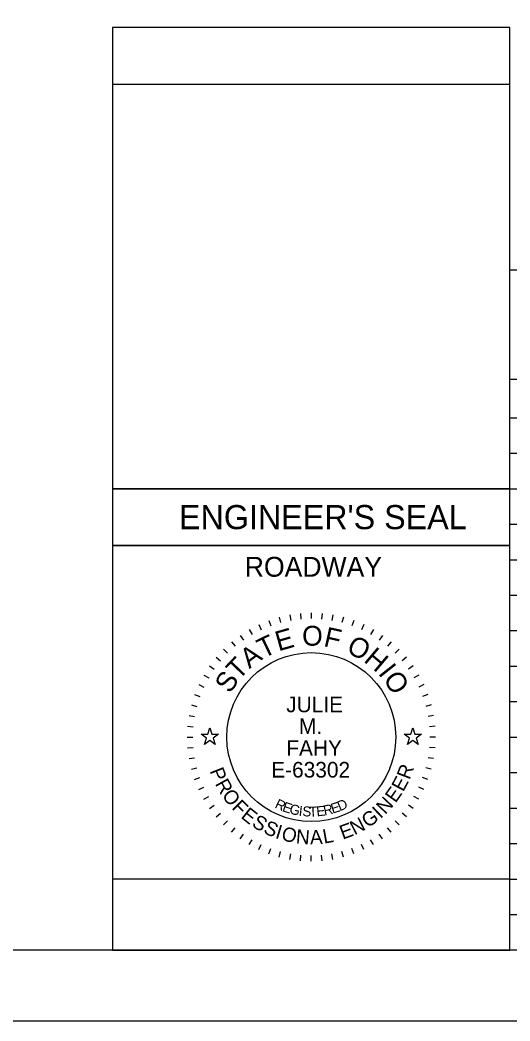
# Model space of a CAD drawing. Extents: x 0 to 34, y 0 to 22.
# Drawn here: x 6.7 to 10.15, y 0 to 7.05 of the extents above; entities that cross this region are included whole.
import ezdxf

# ---------------------------------------------------------------- set-up
doc = ezdxf.new("R2010")
doc.units = 0
for name, color, linetype in [('SH_Border', 7, 'Continuous'), ('SH_Cut_Line', 7, 'Continuous'), ('SH_Data', 7, 'Continuous'), ('SH_Seal', 7, 'Continuous')]:
    doc.layers.add(name, color=color, linetype=linetype)

msp = doc.modelspace()

# ---------------------------------------------------------------- linework, layer by layer
at = {"layer": 'SH_Border'}
msp.add_lwpolyline([(1.5, 21.5), (33.5, 21.5), (33.5, 0.5), (1.5, 0.5)], close=True, dxfattribs=at)
at = {"layer": 'SH_Cut_Line'}
msp.add_lwpolyline([(0, 0), (34, 0), (34, 22), (0, 22)], close=True, dxfattribs=at)
at = {"layer": 'SH_Data'}
for p, q in [((7.35, 6.6), (10.15, 6.6)), ((10.15, 5.2917), (23.6, 5.2917)), ((10.15, 0.5), (10.15, 5.2917)), ((10.15, 4.5209), (23.6, 4.5209)), ((10.15, 4.25), (23.6, 4.25)), ((10.15, 4), (23.6, 4)), ((10.15, 3.75), (7.35, 3.75)), ((7.35, 3.75), (7.35, 0.5)), ((10.15, 0.5), (10.15, 3.75)), ((10.15, 3.75), (23.6, 3.75)), ((10.15, 3.5), (23.6, 3.5)), ((10.15, 3.35), (7.35, 3.35)), ((7.35, 3.35), (10.15, 3.35)), ((10.15, 3.25), (23.6, 3.25)), ((10.15, 3), (23.6, 3)), ((10.15, 2.75), (23.6, 2.75)), ((10.15, 2.5), (23.6, 2.5)), ((10.15, 2.25), (23.6, 2.25)), ((10.15, 2), (23.6, 2)), ((10.15, 1.75), (23.6, 1.75)), ((10.15, 1.5), (23.6, 1.5)), ((10.15, 1.25), (23.6, 1.25)), ((10.15, 1), (23.6, 1)), ((10.15, 0.75), (23.6, 0.75)), ((10.15, 0.5), (7.35, 0.5))]:
    msp.add_line(p, q, dxfattribs=at)
for points in [[(10.15, 7), (7.35, 7), (7.35, 3.75), (10.15, 3.75)], [(10.15, 3.75), (7.35, 3.75), (7.35, 0.5), (10.15, 0.5)], [(10.15, 0.5), (10.15, 1), (7.35, 1), (7.35, 0.5)]]:
    msp.add_lwpolyline(points, close=True, dxfattribs=at)
at = {"layer": 'SH_Seal'}
for p, q in [((8.4507, 2.8222), (8.4644, 2.7846)), ((8.5235, 2.8452), (8.5339, 2.8065)), ((8.5981, 2.8617), (8.605, 2.8223)), ((8.6737, 2.8717), (8.6772, 2.8318)), ((8.75, 2.875), (8.75, 2.835)), ((8.8263, 2.8717), (8.8228, 2.8318)), ((8.9019, 2.8617), (8.895, 2.8223)), ((8.9765, 2.8452), (8.9661, 2.8065)), ((9.0493, 2.8222), (9.0356, 2.7846)), ((8.3125, 2.7578), (8.3325, 2.7231)), ((8.3802, 2.793), (8.3971, 2.7568)), ((9.1198, 2.793), (9.1029, 2.7568)), ((9.1875, 2.7578), (9.1675, 2.7231)), ((8.2481, 2.7168), (8.2711, 2.684)), ((9.2519, 2.7168), (9.2289, 2.684)), ((8.1313, 2.6187), (8.1596, 2.5904)), ((8.1876, 2.6703), (8.2133, 2.6396)), ((9.3124, 2.6703), (9.2867, 2.6396)), ((9.3687, 2.6187), (9.3404, 2.5904)), ((8.0797, 2.5624), (8.1104, 2.5367)), ((9.4203, 2.5624), (9.3896, 2.5367)), ((8.0332, 2.5019), (8.066, 2.4789)), ((9.4668, 2.5019), (9.434, 2.4789)), ((7.9922, 2.4375), (8.0269, 2.4175)), ((9.5078, 2.4375), (9.4731, 2.4175)), ((7.957, 2.3698), (7.9932, 2.3529)), ((9.543, 2.3698), (9.5068, 2.3529)), ((7.9278, 2.2993), (7.9654, 2.2856)), ((9.5722, 2.2993), (9.5346, 2.2856)), ((7.9048, 2.2265), (7.9435, 2.2161)), ((9.5952, 2.2265), (9.5565, 2.2161)), ((7.8883, 2.1519), (7.9277, 2.145)), ((9.6117, 2.1519), (9.5723, 2.145)), ((7.8783, 2.0763), (7.9182, 2.0728)), ((9.6217, 2.0763), (9.5818, 2.0728)), ((7.875, 2), (7.915, 2)), ((9.625, 2), (9.585, 2)), ((7.8783, 1.9237), (7.9182, 1.9272)), ((9.6217, 1.9237), (9.5818, 1.9272)), ((7.8883, 1.8481), (7.9277, 1.855)), ((9.6117, 1.8481), (9.5723, 1.855)), ((7.9048, 1.7735), (7.9435, 1.7839)), ((9.5952, 1.7735), (9.5565, 1.7839)), ((7.9278, 1.7007), (7.9654, 1.7144)), ((9.5722, 1.7007), (9.5346, 1.7144)), ((7.957, 1.6302), (7.9932, 1.6471)), ((9.543, 1.6302), (9.5068, 1.6471)), ((7.9922, 1.5625), (8.0269, 1.5825)), ((9.5078, 1.5625), (9.4731, 1.5825)), ((8.0332, 1.4981), (8.066, 1.5211)), ((9.4668, 1.4981), (9.434, 1.5211)), ((8.0797, 1.4376), (8.1104, 1.4633)), ((9.4203, 1.4376), (9.3896, 1.4633)), ((8.1313, 1.3813), (8.1596, 1.4096)), ((8.1876, 1.3297), (8.2133, 1.3604)), ((9.3124, 1.3297), (9.2867, 1.3604)), ((9.3687, 1.3813), (9.3404, 1.4096)), ((8.2481, 1.2832), (8.2711, 1.316)), ((8.3125, 1.2422), (8.3325, 1.2769)), ((9.1875, 1.2422), (9.1675, 1.2769)), ((9.2519, 1.2832), (9.2289, 1.316)), ((8.3802, 1.207), (8.3971, 1.2432)), ((8.4507, 1.1778), (8.4644, 1.2154)), ((9.0493, 1.1778), (9.0356, 1.2154)), ((9.1198, 1.207), (9.1029, 1.2432)), ((8.5235, 1.1548), (8.5339, 1.1935)), ((8.5981, 1.1383), (8.605, 1.1777)), ((8.6737, 1.1283), (8.6772, 1.1682)), ((8.75, 1.125), (8.75, 1.165)), ((8.8263, 1.1283), (8.8228, 1.1682)), ((8.9019, 1.1383), (8.895, 1.1777)), ((8.9765, 1.1548), (8.9661, 1.1935))]:
    msp.add_line(p, q, dxfattribs=at)
for points in [[(7.9736, 2.02), (8.0205, 2.02), (8.035, 2.0645), (8.0495, 2.02), (8.0964, 2.02), (8.0585, 1.9924), (8.073, 1.9478), (8.035, 1.9754), (7.997, 1.9478), (8.0115, 1.9924)], [(9.4036, 2.02), (9.4505, 2.02), (9.465, 2.0645), (9.4795, 2.02), (9.5264, 2.02), (9.4885, 1.9924), (9.503, 1.9478), (9.465, 1.9754), (9.427, 1.9478), (9.4415, 1.9924)]]:
    msp.add_lwpolyline(points, close=True, dxfattribs=at)
msp.add_circle((8.75, 2), 0.595, dxfattribs=at)

# ---------------------------------------------------------------- texts
at = {"layer": 'SH_Data'}
for s, height, p in [("ENGINEER'S SEAL", 0.17, (7.8176, 3.465)), ('ROADWAY', 0.14, (8.2811, 3.13))]:
    msp.add_text(s, height=height, dxfattribs=at).set_placement(p)
at = {"layer": 'SH_Seal'}
for s, height, rotation, p in [('E', 0.14, 15.75706, (8.5184, 2.6038)), ('O', 0.14, 359.78119, (8.6847, 2.6443)), ('F', 0.14, 347.43619, (8.8311, 2.6417)), ('T', 0.14, 25.71674, (8.4116, 2.5518)), ('O', 0.14, 332.25863, (8.9898, 2.6015)), ('A', 0.14, 36.47472, (8.3134, 2.4781)), ('H', 0.14, 319.91363, (9.1132, 2.5361)), ('T', 0.14, 46.4344, (8.2383, 2.3964)), ('I', 0.14, 308.36695, (9.2165, 2.4483)), ('S', 0.14, 57.19238, (8.1781, 2.3014)), ('O', 0.14, 303.14906, (9.2521, 2.4089)), ('P', 0.1, 291.49398, (8.0323, 1.7621)), ('R', 0.1, 69.23216, (9.4419, 1.6954)), ('R', 0.1, 298.73106, (8.069, 1.6717)), ('E', 0.1, 61.99508, (9.3976, 1.6098)), ('O', 0.1, 306.46664, (8.1155, 1.5883)), ('E', 0.1, 54.75801, (9.3433, 1.5314)), ('F', 0.1, 314.7068, (8.1843, 1.4983)), ('R', 0.07, 334.48695, (8.4875, 1.5051)), ('D', 0.07, 23.30524, (8.951, 1.477)), ('N', 0.1, 47.02243, (9.2702, 1.4508)), ('E', 0.1, 321.43929, (8.2478, 1.4348)), ('E', 0.07, 341.03996, (8.5406, 1.4801)), ('G', 0.07, 347.47515, (8.5914, 1.4618)), ('I', 0.07, 353.78581, (8.6591, 1.4468)), ('S', 0.07, 356.89262, (8.6858, 1.4429)), ('T', 0.07, 3.00609, (8.7357, 1.4387)), ('E', 0.07, 6.01169, (8.7889, 1.4412)), ('R', 0.07, 11.91844, (8.8425, 1.4474)), ('E', 0.07, 17.68363, (8.8998, 1.4602)), ('I', 0.1, 43.28703, (9.2368, 1.4214)), ('S', 0.1, 328.67637, (8.3243, 1.3752)), ('N', 0.1, 27.31129, (9.0545, 1.3075)), ('G', 0.1, 35.04687, (9.1481, 1.357)), ('S', 0.1, 335.91345, (8.4064, 1.3266)), ('I', 0.1, 343.15053, (8.4906, 1.2897)), ('O', 0.1, 346.88592, (8.5339, 1.2751)), ('N', 0.1, 355.12608, (8.6388, 1.2517)), ('A', 0.1, 2.86166, (8.7423, 1.2437)), ('L', 0.1, 10.09874, (8.8394, 1.249)), ('E', 0.1, 20.07421, (8.9712, 1.277))]:
    msp.add_text(s, height=height, rotation=rotation, dxfattribs=at).set_placement(p)
for s, p in [('JULIE', (8.573, 2.1749)), ('M.', (8.6626, 2.0216)), ('FAHY', (8.5734, 1.8684)), ('E-63302', (8.4672, 1.7151))]:
    msp.add_text(s, height=0.11, dxfattribs=at).set_placement(p)

doc.saveas('drawing.dxf')
